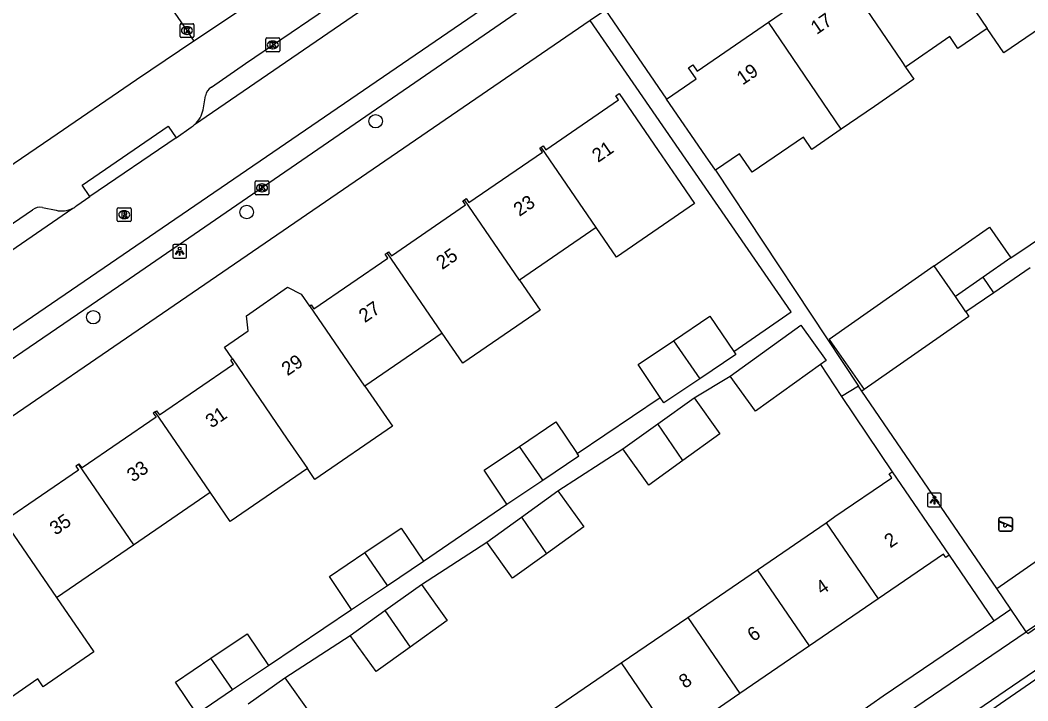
# Model space of a CAD drawing. Extents: x 157466 to 158888, y 383063 to 384677.
# Drawn here: x 158104.2 to 158177.3, y 383502.1 to 383551.5 of the extents above; entities that cross this region are included whole.
import ezdxf

# ---------------------------------------------------------------- set-up
doc = ezdxf.new("R2010")
doc.units = 0
for name, color, linetype in [('IMGEO_Boom', 7, 'Continuous'), ('IMGEO_Groenvoorziening', 7, 'Continuous'), ('IMGEO_Kolk', 7, 'Continuous'), ('IMGEO_Lichtpunt', 7, 'Continuous'), ('IMGEO_Pand', 7, 'Continuous'), ('IMGEO_Pand_nummerreeks', 7, 'Continuous'), ('IMGEO_Rijbaan_lokaal_open', 7, 'Continuous'), ('IMGEO_Rioolput', 7, 'Continuous'), ('IMGEO_Speelvoorziening', 7, 'Continuous'), ('IMGEO_Voetpad_gesloten', 7, 'Continuous'), ('IMGEO_Voetpad_open', 7, 'Continuous')]:
    doc.layers.add(name, color=color, linetype=linetype)

msp = doc.modelspace()

# ---------------------------------------------------------------- linework, layer by layer
at = {"layer": 'IMGEO_Boom'}
for centre in [(158129.944, 383544.171), (158120.593, 383537.585), (158109.454, 383529.958)]:
    msp.add_circle(centre, 0.489, dxfattribs=at)
at = {"layer": 'IMGEO_Groenvoorziening'}
msp.add_lwpolyline([(158165.398, 383524.716), (158165.238, 383524.604)], dxfattribs=at)
at = {"layer": 'IMGEO_Kolk'}
for p, q in [((158115.754, 383550.319), (158115.754, 383551.171)), ((158115.829, 383551.245), (158116.681, 383551.245)), ((158116.242, 383551.025), (158116.267, 383551.025)), ((158116.755, 383551.171), (158116.755, 383550.319)), ((158116.681, 383550.245), (158115.829, 383550.245)), ((158116.265, 383550.465), (158116.24, 383550.465)), ((158121.984, 383549.281), (158121.984, 383550.133)), ((158122.059, 383550.207), (158122.911, 383550.207)), ((158122.472, 383549.987), (158122.497, 383549.987)), ((158122.985, 383550.133), (158122.985, 383549.281)), ((158122.911, 383549.207), (158122.059, 383549.207)), ((158122.495, 383549.427), (158122.47, 383549.427)), ((158121.201, 383538.914), (158121.201, 383539.766)), ((158121.276, 383539.84), (158122.128, 383539.84)), ((158121.689, 383539.62), (158121.714, 383539.62)), ((158122.202, 383539.766), (158122.202, 383538.914)), ((158121.712, 383539.06), (158121.687, 383539.06)), ((158122.128, 383538.84), (158121.276, 383538.84))]:
    msp.add_line(p, q, dxfattribs=at)
for points in [[(158115.754, 383550.319), (158115.754, 383551.171)], [(158115.829, 383551.245), (158116.681, 383551.245)], [(158116.075, 383550.945), (158116.198, 383550.945), (158116.198, 383550.794), (158116.328, 383550.945), (158116.492, 383550.945), (158116.346, 383550.794), (158116.499, 383550.545), (158116.347, 383550.545), (158116.262, 383550.709), (158116.198, 383550.642), (158116.198, 383550.545), (158116.075, 383550.545), (158116.075, 383550.945)], [(158116.755, 383551.171), (158116.755, 383550.319)], [(158116.681, 383550.245), (158115.829, 383550.245)], [(158121.984, 383549.281), (158121.984, 383550.133)], [(158122.059, 383550.207), (158122.911, 383550.207)], [(158122.305, 383549.907), (158122.428, 383549.907), (158122.428, 383549.756), (158122.558, 383549.907), (158122.722, 383549.907), (158122.576, 383549.756), (158122.729, 383549.507), (158122.577, 383549.507), (158122.492, 383549.671), (158122.428, 383549.604), (158122.428, 383549.507), (158122.305, 383549.507), (158122.305, 383549.907)], [(158122.985, 383550.133), (158122.985, 383549.281)], [(158122.911, 383549.207), (158122.059, 383549.207)], [(158121.201, 383538.914), (158121.201, 383539.766)], [(158121.276, 383539.84), (158122.128, 383539.84)], [(158122.202, 383539.766), (158122.202, 383538.914)], [(158121.522, 383539.54), (158121.645, 383539.54), (158121.645, 383539.389), (158121.775, 383539.54), (158121.939, 383539.54), (158121.793, 383539.389), (158121.946, 383539.14), (158121.794, 383539.14), (158121.709, 383539.304), (158121.645, 383539.237), (158121.645, 383539.14), (158121.522, 383539.14), (158121.522, 383539.54)], [(158122.128, 383538.84), (158121.276, 383538.84)]]:
    msp.add_lwpolyline(points, dxfattribs=at)
for centre, start, end in [((158115.831, 383551.169), 91.55205, 178.44795), ((158115.831, 383551.169), 91.55205, 178.44795), ((158116.679, 383551.169), 1.55205, 88.44795), ((158116.679, 383551.169), 1.55205, 88.44795), ((158115.831, 383550.321), 181.55205, 268.44795), ((158115.831, 383550.321), 181.55205, 268.44795), ((158116.679, 383550.321), 271.55205, 358.44795), ((158116.679, 383550.321), 271.55205, 358.44795), ((158122.061, 383550.131), 91.55205, 178.44795), ((158122.061, 383550.131), 91.55205, 178.44795), ((158122.909, 383550.131), 1.55205, 88.44795), ((158122.909, 383550.131), 1.55205, 88.44795), ((158122.061, 383549.283), 181.55205, 268.44795), ((158122.061, 383549.283), 181.55205, 268.44795), ((158122.909, 383549.283), 271.55205, 358.44795), ((158122.909, 383549.283), 271.55205, 358.44795), ((158121.278, 383539.764), 91.55205, 178.44795), ((158121.278, 383539.764), 91.55205, 178.44795), ((158122.126, 383539.764), 1.55205, 88.44795), ((158122.126, 383539.764), 1.55205, 88.44795), ((158121.278, 383538.916), 181.55205, 268.44795), ((158121.278, 383538.916), 181.55205, 268.44795), ((158122.126, 383538.916), 271.55205, 358.44795), ((158122.126, 383538.916), 271.55205, 358.44795)]:
    msp.add_arc(centre, 0.0765, start, end, dxfattribs=at)
for centre, major_axis, ratio, start_param, end_param in [((158116.241, 383550.745), (-0.387, 0.002), 0.722429, 4.712389, 7.853982), ((158116.266, 383550.745), (-0.39, 0.002), 0.717154, 1.570796, 4.712389), ((158122.471, 383549.707), (-0.387, 0.002), 0.722429, 4.712389, 7.853982), ((158122.496, 383549.707), (-0.39, 0.002), 0.717154, 1.570796, 4.712389), ((158121.688, 383539.34), (-0.387, 0.002), 0.722429, 4.712389, 7.853982), ((158121.713, 383539.34), (-0.39, 0.002), 0.717154, 1.570796, 4.712389)]:
    msp.add_ellipse(centre, major_axis=major_axis, ratio=ratio, start_param=start_param, end_param=end_param, dxfattribs=at)
at = {"layer": 'IMGEO_Lichtpunt'}
for p, q in [((158116.128, 383535.229), (158115.32, 383535.229)), ((158116.128, 383535.229), (158115.32, 383535.229)), ((158115.226, 383535.134), (158115.226, 383534.327)), ((158115.226, 383535.134), (158115.226, 383534.327)), ((158116.222, 383534.327), (158116.222, 383535.134)), ((158116.222, 383534.327), (158116.222, 383535.134)), ((158115.32, 383534.233), (158116.128, 383534.233)), ((158115.32, 383534.233), (158116.128, 383534.233)), ((158169.996, 383517.1), (158169.996, 383516.293)), ((158169.996, 383517.1), (158169.996, 383516.293)), ((158170.898, 383517.195), (158170.09, 383517.195)), ((158170.898, 383517.195), (158170.09, 383517.195)), ((158170.992, 383516.293), (158170.992, 383517.1)), ((158170.992, 383516.293), (158170.992, 383517.1)), ((158170.09, 383516.199), (158170.898, 383516.199)), ((158170.09, 383516.199), (158170.898, 383516.199))]:
    msp.add_line(p, q, dxfattribs=at)
for points in [[(158115.6, 383534.798), (158115.639, 383534.77), (158115.451, 383534.508), (158115.413, 383534.535), (158115.6, 383534.798)], [(158115.702, 383534.75), (158115.749, 383534.75), (158115.749, 383534.428), (158115.702, 383534.428), (158115.702, 383534.75)], [(158115.812, 383534.77), (158115.85, 383534.797), (158116.037, 383534.535), (158115.998, 383534.507), (158115.812, 383534.77)], [(158170.37, 383516.764), (158170.409, 383516.736), (158170.221, 383516.474), (158170.183, 383516.501), (158170.37, 383516.764)], [(158170.472, 383516.716), (158170.519, 383516.716), (158170.519, 383516.394), (158170.472, 383516.394), (158170.472, 383516.716)], [(158170.582, 383516.736), (158170.62, 383516.763), (158170.807, 383516.501), (158170.768, 383516.473), (158170.582, 383516.736)]]:
    msp.add_lwpolyline(points, dxfattribs=at)
for centre in [(158115.725, 383534.932), (158170.495, 383516.898)]:
    msp.add_circle(centre, 0.0994, dxfattribs=at)
for centre, start, end in [((158115.32, 383535.134), 90, 180), ((158115.32, 383535.134), 90, 180), ((158116.128, 383535.134), 0, 90), ((158116.128, 383535.134), 0, 90), ((158115.32, 383534.327), 180, 270), ((158115.32, 383534.327), 180, 270), ((158116.128, 383534.327), 270, 0), ((158116.128, 383534.327), 270, 360), ((158170.09, 383517.1), 90, 180), ((158170.09, 383517.1), 90, 180), ((158170.898, 383517.1), 0, 90), ((158170.898, 383517.1), 0, 90), ((158170.09, 383516.293), 180, 270), ((158170.09, 383516.293), 180, 270), ((158170.898, 383516.293), 270, 0), ((158170.898, 383516.293), 270, 360)]:
    msp.add_arc(centre, 0.0946, start, end, dxfattribs=at)
at = {"layer": 'IMGEO_Pand'}
for points in [[(158169.063, 383558.62), (158174.327, 383550.898)], [(158158.447, 383551.345), (158163.204, 383554.615), (158163.719, 383554.969)], [(158163.719, 383554.969), (158168.125, 383548.508), (158168.405, 383548.098)], [(158178.996, 383555.316), (158180.776, 383552.705), (158175.532, 383549.13), (158174.327, 383550.898)], [(158151.064, 383545.779), (158153.2, 383547.245), (158152.648, 383548.048), (158152.967, 383548.268), (158153.289, 383547.799), (158158.447, 383551.345)], [(158163.737, 383543.59), (158158.447, 383551.345)], [(158174.327, 383550.898), (158172.206, 383549.44), (158171.613, 383550.303), (158168.405, 383548.098)], [(158168.405, 383548.098), (158169.008, 383547.214), (158166.141, 383545.243), (158163.737, 383543.59)], [(158141.955, 383542.291), (158142.097, 383542.388), (158142.295, 383542.1), (158147.571, 383545.716), (158147.373, 383546.004), (158147.623, 383546.176), (158150.45, 383542.052), (158151.784, 383540.105), (158153.087, 383538.205), (158147.417, 383534.318), (158145.945, 383536.466)], [(158154.607, 383540.617), (158153.893, 383541.657), (158151.064, 383545.779)], [(158163.737, 383543.59), (158161.609, 383542.127), (158160.992, 383543.026), (158157.266, 383540.465), (158156.343, 383541.809), (158154.607, 383540.617)], [(158136.39, 383538.476), (158136.522, 383538.566), (158136.719, 383538.278), (158142.048, 383541.93), (158141.85, 383542.218), (158141.955, 383542.291)], [(158145.945, 383536.466), (158141.955, 383542.291)], [(158130.78, 383534.63), (158130.888, 383534.704), (158131.086, 383534.416), (158136.472, 383538.108), (158136.274, 383538.396), (158136.39, 383538.476)], [(158140.38, 383532.652), (158136.39, 383538.476)], [(158145.945, 383536.466), (158140.38, 383532.652)], [(158170.489, 383533.691), (158174.495, 383536.489), (158176.046, 383534.268)], [(158125.178, 383530.789), (158125.271, 383530.853), (158125.469, 383530.566), (158130.839, 383534.246), (158130.641, 383534.534), (158130.78, 383534.63)], [(158134.77, 383528.806), (158130.78, 383534.63)], [(158176.046, 383534.268), (158174.031, 383532.861)], [(158170.489, 383533.691), (158162.86, 383528.351), (158165.398, 383524.716)], [(158172.016, 383531.454), (158170.489, 383533.691)], [(158140.38, 383532.652), (158141.877, 383530.467), (158136.266, 383526.622), (158134.77, 383528.806)], [(158174.031, 383532.861), (158172.016, 383531.454)], [(158119.549, 383526.931), (158119.564, 383526.941), (158118.974, 383527.792), (158120.697, 383528.972), (158120.566, 383530.069), (158123.56, 383532.14), (158124.544, 383531.627), (158125.139, 383530.762), (158125.178, 383530.789)], [(158172.774, 383530.341), (158172.016, 383531.454)], [(158129.168, 383524.966), (158125.178, 383530.789)], [(158172.774, 383530.341), (158172.993, 383530.02), (158165.398, 383524.716)], [(158151.571, 383528.252), (158154.21, 383530.028), (158155.935, 383527.463)], [(158155.682, 383525.692), (158160.796, 383529.376), (158162.635, 383526.823), (158162.22, 383526.524)], [(158134.77, 383528.806), (158129.168, 383524.966)], [(158150.6, 383524.142), (158148.999, 383526.522), (158151.571, 383528.252)], [(158151.571, 383528.252), (158153.462, 383525.491)], [(158155.935, 383527.463), (158156.078, 383527.251), (158153.462, 383525.491)], [(158113.949, 383523.092), (158114.054, 383523.164), (158114.251, 383522.876), (158119.629, 383526.563), (158119.432, 383526.85), (158119.549, 383526.931)], [(158119.549, 383526.931), (158123.539, 383521.107), (158124.998, 383518.978)], [(158162.22, 383526.524), (158157.521, 383523.139), (158155.682, 383525.692)], [(158129.168, 383524.966), (158131.163, 383522.057), (158125.533, 383518.197), (158124.998, 383518.978)], [(158153.462, 383525.491), (158150.867, 383523.745), (158150.6, 383524.142)], [(158150.415, 383522.225), (158153.055, 383524.121)], [(158153.055, 383524.121), (158154.935, 383521.503), (158152.235, 383519.564)], [(158113.949, 383523.092), (158113.815, 383523), (158114.012, 383522.712), (158108.643, 383519.031), (158108.445, 383519.319), (158108.377, 383519.272)], [(158117.939, 383517.268), (158113.949, 383523.092)], [(158140.397, 383520.593), (158143.035, 383522.368), (158144.57, 383520.086)], [(158147.886, 383520.409), (158150.415, 383522.225)], [(158152.235, 383519.564), (158150.415, 383522.225)], [(158139.479, 383516.402), (158137.824, 383518.862), (158140.397, 383520.593)], [(158142.072, 383518.147), (158140.397, 383520.593)], [(158142.072, 383518.147), (158144.69, 383519.908), (158144.57, 383520.086)], [(158152.235, 383519.564), (158149.766, 383517.791), (158147.886, 383520.409)], [(158108.377, 383519.272), (158108.198, 383519.149), (158108.395, 383518.862), (158103.026, 383515.181), (158102.827, 383515.467), (158102.8, 383515.449)], [(158108.377, 383519.272), (158112.367, 383513.448)], [(158124.998, 383518.978), (158119.396, 383515.141), (158117.939, 383517.268)], [(158162.637, 383515.057), (158163.279, 383515.496), (158167.406, 383518.318), (158167.207, 383518.605), (158167.427, 383518.752)], [(158167.427, 383518.752), (158171.578, 383512.706)], [(158139.479, 383516.402), (158142.072, 383518.147)], [(158112.367, 383513.448), (158117.939, 383517.268)], [(158140.533, 383515.468), (158143.174, 383517.364)], [(158143.174, 383517.364), (158145.054, 383514.746), (158142.353, 383512.807)], [(158138.005, 383513.652), (158140.533, 383515.468)], [(158140.533, 383515.468), (158142.353, 383512.807)], [(158102.8, 383515.449), (158106.79, 383509.625)], [(158157.65, 383511.646), (158162.637, 383515.057)], [(158162.637, 383515.057), (158166.413, 383509.536)], [(158129.166, 383512.894), (158131.804, 383514.669), (158133.415, 383512.274)], [(158106.79, 383509.625), (158112.367, 383513.448)], [(158142.353, 383512.807), (158139.885, 383511.034), (158138.005, 383513.652)], [(158128.204, 383508.768), (158126.593, 383511.163), (158129.166, 383512.894)], [(158130.797, 383510.512), (158129.166, 383512.894)], [(158171.578, 383512.706), (158171.33, 383512.536), (158171.16, 383512.783), (158166.413, 383509.536)], [(158130.797, 383510.512), (158133.415, 383512.274)], [(158152.593, 383508.188), (158157.65, 383511.646)], [(158161.426, 383506.125), (158157.65, 383511.646)], [(158128.204, 383508.768), (158130.797, 383510.512)], [(158130.624, 383508.691), (158133.265, 383510.587)], [(158133.265, 383510.587), (158135.145, 383507.969), (158132.444, 383506.03)], [(158106.79, 383509.625), (158109.493, 383505.682), (158105.819, 383503.163), (158105.435, 383503.723), (158103.459, 383502.368), (158103.08, 383502.92)], [(158166.413, 383509.536), (158161.426, 383506.125)], [(158128.096, 383506.875), (158130.624, 383508.691)], [(158130.624, 383508.691), (158132.444, 383506.03)], [(158147.769, 383504.889), (158152.593, 383508.188)], [(158152.593, 383508.188), (158156.37, 383502.667)], [(158178.381, 383496.502), (158175.975, 383500), (158175.016, 383501.394), (158174.769, 383501.224), (158174.599, 383501.472), (158180.671, 383505.651), (158183.436, 383507.554), (158187.003, 383502.372), (158184.227, 383500.482)], [(158117.994, 383505.235), (158120.632, 383507.01), (158122.177, 383504.713)], [(158132.444, 383506.03), (158129.976, 383504.257), (158128.096, 383506.875)], [(158161.426, 383506.125), (158156.37, 383502.667)], [(158116.966, 383501.207), (158115.421, 383503.504), (158117.994, 383505.235)], [(158119.558, 383502.951), (158117.994, 383505.235)], [(158119.558, 383502.951), (158122.177, 383504.713)], [(158142.851, 383501.526), (158147.769, 383504.889)], [(158147.769, 383504.889), (158151.113, 383500), (158151.545, 383499.368)], [(158120.708, 383501.911), (158123.349, 383503.807)], [(158123.349, 383503.807), (158125.229, 383501.189), (158122.528, 383499.25)], [(158116.966, 383501.207), (158119.558, 383502.951)], [(158156.37, 383502.667), (158152.47, 383500), (158151.545, 383499.368)]]:
    msp.add_lwpolyline(points, dxfattribs=at)
at = {"layer": 'IMGEO_Rijbaan_lokaal_open'}
for points in [[(158116.811, 383543.924), (158152.495, 383568.394)], [(158106.53, 383564.786), (158116.252, 383550.745), (158116.761, 383549.981)], [(158073.425, 383508.419), (158154.999, 383564.17)], [(158116.761, 383549.981), (158112.582, 383547.184), (158106.37, 383542.921), (158102.097, 383540.018)], [(158115.46, 383542.976), (158116.571, 383543.735)], [(158115.46, 383542.976), (158109.217, 383538.71)], [(158108.258, 383538.055), (158109.217, 383538.71)], [(158071.476, 383512.786), (158107.966, 383537.858)]]:
    msp.add_lwpolyline(points, dxfattribs=at)
for centre, radius, start, end in [((158115.492, 383545.352), 1.944, 303.71378, 312.72709), ((158107.152, 383539.379), 1.725, 298.14624, 309.8655)]:
    msp.add_arc(centre, radius, start, end, dxfattribs=at)
at = {"layer": 'IMGEO_Rioolput'}
for p, q in [((158111.202, 383536.969), (158111.202, 383537.821)), ((158111.277, 383537.895), (158112.129, 383537.895)), ((158111.69, 383537.675), (158111.715, 383537.675)), ((158112.203, 383537.821), (158112.203, 383536.969)), ((158112.129, 383536.895), (158111.277, 383536.895)), ((158111.713, 383537.115), (158111.688, 383537.115))]:
    msp.add_line(p, q, dxfattribs=at)
for points in [[(158111.202, 383536.969), (158111.202, 383537.821)], [(158111.277, 383537.895), (158112.129, 383537.895)], [(158111.791, 383537.593), (158111.539, 383537.595), (158111.539, 383537.195)], [(158111.717, 383537.514), (158111.663, 383537.514), (158111.663, 383537.433)], [(158111.663, 383537.433), (158111.715, 383537.433)], [(158112.203, 383537.821), (158112.203, 383536.969)], [(158112.129, 383536.895), (158111.277, 383536.895)], [(158111.539, 383537.195), (158111.663, 383537.195), (158111.663, 383537.357), (158111.674, 383537.357)], [(158111.721, 383537.328), (158111.792, 383537.195), (158111.932, 383537.195), (158111.867, 383537.321)]]:
    msp.add_lwpolyline(points, dxfattribs=at)
for centre, radius, start, end in [((158111.279, 383537.819), 0.0765, 91.55205, 178.44795), ((158111.279, 383537.819), 0.0765, 91.55205, 178.44795), ((158111.699, 383537.622), 0.19, 274.7715, 282.96867), ((158111.723, 383537.418), 0.0964, 77.00612, 93.18647), ((158111.737, 383537.475), 0.0378, 276.66336, 79.67722), ((158111.79, 383537.483), 0.109, 350.36119, 89.41601), ((158111.788, 383537.483), 0.112, 277.58423, 350.98172), ((158112.127, 383537.819), 0.0765, 1.55205, 88.44795), ((158112.127, 383537.819), 0.0765, 1.55205, 88.44795), ((158111.279, 383536.971), 0.0765, 181.55205, 268.44795), ((158111.279, 383536.971), 0.0765, 181.55205, 268.44795), ((158111.673, 383537.304), 0.0533, 26.02933, 88.69889), ((158111.772, 383537.268), 0.108, 29.51342, 73.79051), ((158112.127, 383536.971), 0.0765, 271.55205, 358.44795), ((158112.127, 383536.971), 0.0765, 271.55205, 358.44795)]:
    msp.add_arc(centre, radius, start, end, dxfattribs=at)
for centre, major_axis, ratio, start_param, end_param in [((158111.689, 383537.395), (-0.387, 0.002), 0.722429, 4.712389, 7.853982), ((158111.714, 383537.395), (-0.39, 0.002), 0.717154, 1.570796, 4.712389)]:
    msp.add_ellipse(centre, major_axis=major_axis, ratio=ratio, start_param=start_param, end_param=end_param, dxfattribs=at)
at = {"layer": 'IMGEO_Speelvoorziening'}
for p, q in [((158175.163, 383514.536), (158175.163, 383515.336)), ((158175.163, 383515.336), (158175.163, 383514.536)), ((158175.546, 383514.964), (158175.207, 383515.101)), ((158175.232, 383515.161), (158176.108, 383514.808)), ((158175.263, 383515.436), (158176.053, 383515.436)), ((158176.053, 383515.436), (158175.263, 383515.436)), ((158176.084, 383514.748), (158175.744, 383514.885)), ((158176.153, 383515.336), (158176.153, 383514.536)), ((158176.153, 383514.536), (158176.153, 383515.336)), ((158176.053, 383514.436), (158175.263, 383514.436)), ((158175.263, 383514.436), (158176.053, 383514.436))]:
    msp.add_line(p, q, dxfattribs=at)
for centre, radius, start, end in [((158175.263, 383515.336), 0.1, 90, 180), ((158175.263, 383515.336), 0.1, 90, 180), ((158175.22, 383515.131), 0.0327, 68.07798, 248.07798), ((158175.625, 383514.874), 0.12, 130.99278, 5.16318), ((158176.053, 383515.336), 0.1, 0, 90), ((158176.053, 383515.336), 0.1, 360, 90), ((158176.096, 383514.778), 0.0327, 248.07798, 68.07798), ((158175.263, 383514.536), 0.1, 180, 270), ((158175.263, 383514.536), 0.1, 180, 270), ((158176.053, 383514.536), 0.1, 270, 0), ((158176.053, 383514.536), 0.1, 270, 0)]:
    msp.add_arc(centre, radius, start, end, dxfattribs=at)
at = {"layer": 'IMGEO_Voetpad_gesloten'}
for points in [[(158174.805, 383531.725), (158174.031, 383532.861)], [(158174.805, 383531.725), (158172.774, 383530.341)]]:
    msp.add_lwpolyline(points, dxfattribs=at)
at = {"layer": 'IMGEO_Voetpad_open'}
for points in [[(158152.387, 383573.703), (158116.761, 383549.981)], [(158118.033, 383546.64), (158120.496, 383548.354), (158141.584, 383562.69), (158146.07, 383565.884), (158149.756, 383568.404)], [(158153.534, 383561.259), (158149.836, 383558.736), (158147.366, 383556.977), (158144.483, 383554.996), (158111.298, 383532.192), (158079.99, 383510.832), (158076.698, 383508.583)], [(158146.633, 383552.236), (158145.517, 383551.473)], [(158146.633, 383552.236), (158151.064, 383545.779)], [(158145.517, 383551.473), (158070.298, 383500), (158069.597, 383499.52)], [(158155.935, 383527.463), (158160.102, 383530.339), (158145.517, 383551.473)], [(158117.435, 383545.005), (158117.606, 383546.013)], [(158109.217, 383538.71), (158108.647, 383539.544), (158114.89, 383543.81), (158115.46, 383542.976)], [(158154.607, 383540.617), (158164.997, 383524.956)], [(158072.566, 383515.469), (158075.423, 383517.427), (158087.797, 383525.881), (158101.733, 383535.497), (158105.055, 383537.739)], [(158105.779, 383537.914), (158106.752, 383537.715)], [(158176.046, 383534.268), (158178.852, 383536.141)], [(158177.454, 383533.53), (158174.805, 383531.725)], [(158162.22, 383526.524), (158163.765, 383524.218)], [(158153.055, 383524.121), (158155.682, 383525.692)], [(158164.997, 383524.956), (158163.765, 383524.218)], [(158165.238, 383524.604), (158164.997, 383524.956)], [(158175.02, 383510.296), (158173.875, 383511.97), (158165.238, 383524.604)], [(158144.57, 383520.086), (158150.6, 383524.142)], [(158163.765, 383524.218), (158167.427, 383518.752)], [(158143.174, 383517.364), (158147.886, 383520.409)], [(158175.02, 383510.296), (158185.458, 383517.539), (158187.716, 383514.31), (158177.152, 383507.139)], [(158133.415, 383512.274), (158139.479, 383516.402)], [(158177.152, 383507.139), (158177.273, 383507.024), (158189.663, 383515.631)], [(158133.265, 383510.587), (158138.005, 383513.652)], [(158171.578, 383512.706), (158174.8, 383507.947)], [(158169.458, 383498.667), (158186.515, 383510.296)], [(158176.033, 383508.796), (158175.02, 383510.296)], [(158122.177, 383504.713), (158128.204, 383508.768)], [(158174.8, 383507.947), (158176.033, 383508.796)], [(158177.152, 383507.139), (158176.033, 383508.796)], [(158112.557, 383465.403), (158163.191, 383500), (158166.785, 383502.503), (158174.8, 383507.947)], [(158123.349, 383503.807), (158128.096, 383506.875)], [(158167.926, 383500.89), (158177.152, 383507.139)]]:
    msp.add_lwpolyline(points, dxfattribs=at)
for centre, radius, start, end in [((158118.524, 383545.847), 0.933, 121.75754, 169.73111), ((158115.401, 383545.459), 2.084, 312.58101, 347.42819), ((158105.594, 383537.092), 0.842, 77.33952, 129.83745), ((158107.176, 383539.339), 1.678, 255.36369, 298.07241)]:
    msp.add_arc(centre, radius, start, end, dxfattribs=at)

# ---------------------------------------------------------------- texts
at = {"layer": 'IMGEO_Pand_nummerreeks'}
for s, rotation, p in [('17', 34.28006, (158161.951, 383550.42)), ('19', 34.28164, (158156.576, 383546.756)), ('21', 34.47936, (158146.087, 383541.142)), ('23', 34.47936, (158140.383, 383537.225)), ('25', 34.4806, (158134.773, 383533.372)), ('27', 34.47936, (158129.162, 383529.519)), ('29', 34.4806, (158123.552, 383525.666)), ('31', 34.4806, (158118.035, 383521.877)), ('33', 34.4806, (158112.331, 383517.96)), ('35', 34.4806, (158106.721, 383514.107)), ('2', 34.35991, (158167.291, 383513.187)), ('4', 34.35991, (158162.322, 383509.789)), ('6', 34.35991, (158157.352, 383506.391)), ('8', 34.35991, (158152.384, 383502.994))]:
    msp.add_text(s, height=1, rotation=rotation, dxfattribs=at).set_placement(p)

doc.saveas('drawing.dxf')
